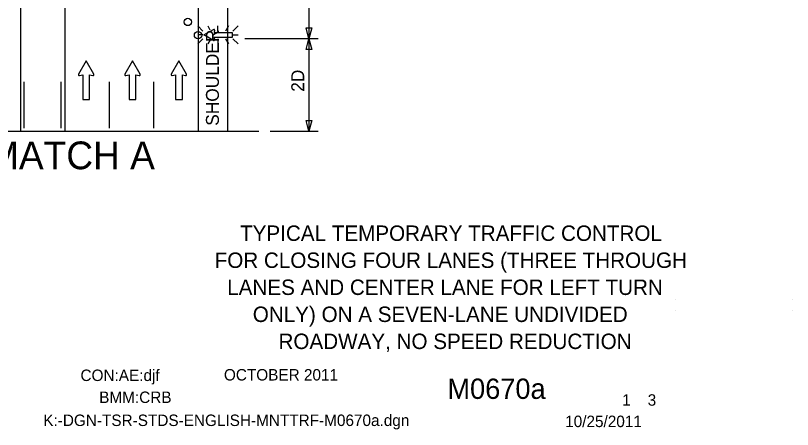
# Model space of a CAD drawing. Extents: x 16038 to 19504, y 5920 to 8321.
# Drawn here: x 17055.6 to 17475.9, y 7218.1 to 7442.1 of the extents above; entities that cross this region are included whole.
import ezdxf

# ---------------------------------------------------------------- set-up
doc = ezdxf.new("R2010")
doc.units = 0
for name, color, linetype in [('ALI_LEGAL_EX', 7, 'Continuous'), ('BORDER', 7, 'Continuous'), ('BORDER_SIGNAL_WO', 7, 'Continuous'), ('MT_SCRATCH_LEVEL_E', 7, 'Continuous'), ('PAVT_EDGE_EX', 7, 'Continuous'), ('TRAFFIC_SIGNS_PR', 7, 'Continuous'), ('TYPICAL_TEXT_DIMEN_PR', 7, 'Continuous')]:
    doc.layers.add(name, color=color, linetype=linetype)

msp = doc.modelspace()

# ---------------------------------------------------------------- linework, layer by layer
at = {"layer": 'ALI_LEGAL_EX'}
for points in [[(17060.3, 7381.21), (17060.3, 7406.21)], [(17080.3, 7381.21), (17080.3, 7406.21)], [(17106.3, 7381.21), (17106.3, 7406.21)], [(17130.3, 7381.21), (17130.3, 7406.21)]]:
    msp.add_lwpolyline(points, dxfattribs=at)
at = {"layer": 'BORDER'}
for p, q in [((17289.25, 7291.25), (17289.25, 7291.25)), ((17412.88, 7288.58), (17412.88, 7288.58)), ((17475.9, 7288.58), (17475.9, 7288.58)), ((17412.88, 7282.34), (17412.88, 7282.34)), ((17475.9, 7282.34), (17475.9, 7282.34))]:
    msp.add_line(p, q, dxfattribs=at)
at = {"layer": 'MT_SCRATCH_LEVEL_E'}
for p, q in [((17093.74, 7417.64), (17089.63, 7410.4)), ((17093.74, 7417.64), (17089.63, 7410.4)), ((17097.88, 7410.4), (17093.74, 7417.64)), ((17097.88, 7410.4), (17093.74, 7417.64)), ((17118.83, 7417.64), (17114.72, 7410.4)), ((17118.83, 7417.64), (17114.72, 7410.4)), ((17122.97, 7410.4), (17118.83, 7417.64)), ((17122.97, 7410.4), (17118.83, 7417.64)), ((17143.92, 7417.64), (17139.81, 7410.4)), ((17143.92, 7417.64), (17139.81, 7410.4)), ((17148.06, 7410.4), (17143.92, 7417.64)), ((17148.06, 7410.4), (17143.92, 7417.64)), ((17090.11, 7409.71), (17091.89, 7410.03)), ((17090.11, 7409.71), (17091.89, 7410.03)), ((17091.89, 7410.03), (17091.89, 7396.77)), ((17091.89, 7410.03), (17091.89, 7396.77)), ((17095.63, 7396.77), (17095.63, 7410.03)), ((17095.63, 7410.03), (17097.4, 7409.71)), ((17095.63, 7396.77), (17095.63, 7410.03)), ((17095.63, 7410.03), (17097.4, 7409.71)), ((17115.2, 7409.71), (17116.97, 7410.03)), ((17115.2, 7409.71), (17116.97, 7410.03)), ((17116.97, 7410.03), (17116.97, 7396.77)), ((17116.97, 7410.03), (17116.97, 7396.77)), ((17120.72, 7396.77), (17120.72, 7410.03)), ((17120.72, 7410.03), (17122.49, 7409.71)), ((17120.72, 7396.77), (17120.72, 7410.03)), ((17120.72, 7410.03), (17122.49, 7409.71)), ((17140.29, 7409.71), (17142.06, 7410.03)), ((17140.29, 7409.71), (17142.06, 7410.03)), ((17142.06, 7410.03), (17142.06, 7396.77)), ((17142.06, 7410.03), (17142.06, 7396.77)), ((17145.81, 7396.77), (17145.81, 7410.03)), ((17145.81, 7410.03), (17147.58, 7409.71)), ((17145.81, 7396.77), (17145.81, 7410.03)), ((17145.81, 7410.03), (17147.58, 7409.71)), ((17091.89, 7396.77), (17095.63, 7396.77)), ((17091.89, 7396.77), (17095.63, 7396.77)), ((17116.97, 7396.77), (17120.72, 7396.77)), ((17116.97, 7396.77), (17120.72, 7396.77)), ((17142.06, 7396.77), (17145.81, 7396.77)), ((17142.06, 7396.77), (17145.81, 7396.77))]:
    msp.add_line(p, q, dxfattribs=at)
for centre, start, end in [((17090.03, 7410.17), 150.4248, 279.9638), ((17090.03, 7410.17), 150.4248, 279.9638), ((17097.47, 7410.17), 260.0362, 29.7731), ((17097.47, 7410.17), 260.0362, 29.7731), ((17115.12, 7410.17), 150.4248, 279.9638), ((17115.12, 7410.17), 150.4248, 279.9638), ((17122.56, 7410.17), 260.0362, 29.7731), ((17122.56, 7410.17), 260.0362, 29.7731), ((17140.21, 7410.17), 150.4248, 279.9638), ((17140.21, 7410.17), 150.4248, 279.9638), ((17147.65, 7410.17), 260.0362, 29.7731), ((17147.65, 7410.17), 260.0362, 29.7731)]:
    msp.add_arc(centre, 0.463, start, end, dxfattribs=at)
at = {"layer": 'PAVT_EDGE_EX'}
for p, q in [((17154.3, 8211.37), (17154.3, 7379.53)), ((17170.3, 8211.37), (17170.3, 7379.53)), ((17058.3, 7652.9), (17058.3, 7379.53)), ((17082.3, 7625.58), (17082.3, 7379.53))]:
    msp.add_line(p, q, dxfattribs=at)
at = {"layer": 'TRAFFIC_SIGNS_PR'}
for p, q in [((17154.12, 7436.48), (17156.94, 7433.66)), ((17159.55, 7436.48), (17160.76, 7434.39)), ((17165.02, 7433.66), (17165.02, 7436.48)), ((17170.81, 7436.48), (17169.18, 7433.66)), ((17173.11, 7433.66), (17175.93, 7436.48)), ((17156.94, 7431.63), (17154.12, 7431.63)), ((17154.12, 7426.78), (17156.94, 7429.6)), ((17160.84, 7428.96), (17159.58, 7426.78)), ((17165.02, 7429.6), (17165.02, 7426.78)), ((17169.16, 7429.6), (17170.79, 7426.78)), ((17173.11, 7431.63), (17175.93, 7431.63)), ((17173.11, 7429.6), (17175.93, 7426.78))]:
    msp.add_line(p, q, dxfattribs=at)
for points in [[(17162.7, 7428.62), (17157.39, 7431.63), (17162.7, 7434.67)], [(17163.2, 7434.31), (17162.97, 7433.02), (17172.69, 7433.02), (17172.69, 7430.27), (17162.97, 7430.27), (17163.2, 7428.97)]]:
    msp.add_lwpolyline(points, dxfattribs=at)
for centre in [(17148.79, 7438.66), (17154.29, 7431.53)]:
    msp.add_circle(centre, 2, dxfattribs=at)
for centre, start, end in [((17162.86, 7434.37), 350.0407, 118.5167), ((17162.86, 7428.91), 241.1084, 9.2692)]:
    msp.add_arc(centre, 0.341, start, end, dxfattribs=at)
at = {"layer": 'TYPICAL_TEXT_DIMEN_PR'}
for p, q in [((17214.3, 7460.05), (17214.3, 7429.53)), ((17214.3, 7429.53), (17212.73, 7435.4)), ((17212.73, 7435.4), (17214.3, 7435.4)), ((17214.3, 7435.4), (17215.87, 7435.4)), ((17215.87, 7435.4), (17214.3, 7429.53)), ((17219.3, 7429.53), (17179.57, 7429.53)), ((17212.73, 7423.67), (17214.3, 7429.53)), ((17214.3, 7429.53), (17214.3, 7379.53)), ((17214.3, 7429.53), (17215.87, 7423.67)), ((17214.3, 7423.67), (17212.73, 7423.67)), ((17215.87, 7423.67), (17214.3, 7423.67)), ((17214.3, 7379.53), (17212.73, 7385.4)), ((17212.73, 7385.4), (17214.3, 7385.4)), ((17214.3, 7385.4), (17215.87, 7385.4)), ((17215.87, 7385.4), (17214.3, 7379.53)), ((16946.19, 7379.53), (17187.1, 7379.53)), ((17193.3, 7379.53), (17219.3, 7379.53))]:
    msp.add_line(p, q, dxfattribs=at)

# ---------------------------------------------------------------- texts
at = {"layer": 'BORDER'}
for s, p in [('TYPICAL TEMPORARY TRAFFIC CONTROL', (17177.02, 7320.15)), ('FOR CLOSING FOUR LANES (THREE THROUGH', (17163.29, 7305.52)), ('LANES AND CENTER LANE FOR LEFT TURN', (17170.07, 7290.89)), ('ONLY) ON A SEVEN-LANE UNDIVIDED', (17183.91, 7276.26)), ('ROADWAY, NO SPEED REDUCTION', (17197.83, 7261.63))]:
    msp.add_text(s, height=8.348, dxfattribs=at).set_placement(p)
at = {"layer": 'BORDER_SIGNAL_WO'}
for s, height, p in [('CON:AE:djf', 6.2, (17090.69, 7244.31)), ('    OCTOBER 2011    ', 6.2, (17159.08, 7244.59)), ('    M0670a   ', 11, (17272.86, 7234.63)), ('BMM:CRB   ', 6.2, (17100.81, 7232.42)), (' 1    3 ', 6.2, (17381.45, 7230.95)), ('K:-DGN-TSR-STDS-ENGLISH-MNTTRF-M0670a.dgn        ', 6.2, (17070.55, 7219.96)), ('10/25/2011    ', 6.2, (17352.93, 7219.38))]:
    msp.add_text(s, height=height, dxfattribs=at).set_placement(p)
at = {"layer": 'TYPICAL_TEXT_DIMEN_PR'}
for s, p in [('SHOULDER', (17165.58, 7382.47)), ('2D', (17211.74, 7400.88))]:
    msp.add_text(s, height=7, rotation=90, dxfattribs=at).set_placement(p)
msp.add_text('A MATCH A', height=15, dxfattribs=at).set_placement((17021.72, 7358.96))

doc.saveas('drawing.dxf')
